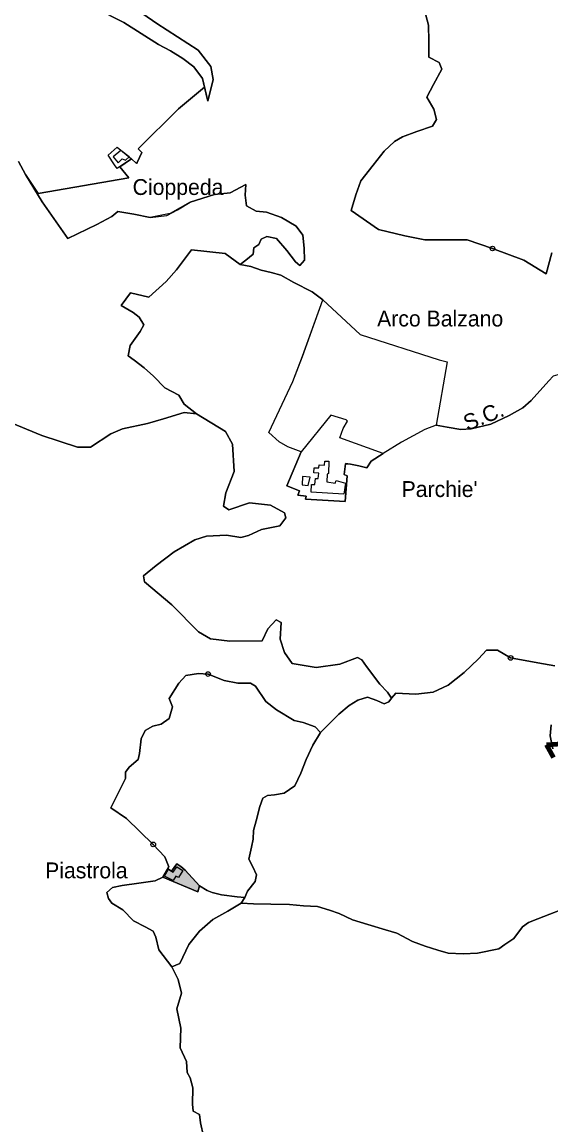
# Model space of a CAD drawing. Extents: x 645880 to 658994, y 884400 to 894744.
# Drawn here: x 652718 to 653285, y 890509 to 891691 of the extents above; entities that cross this region are included whole.
import ezdxf
from ezdxf.enums import TextEntityAlignment as Align

# ---------------------------------------------------------------- set-up
doc = ezdxf.new("R2010")
doc.units = 0
doc.header["$LTSCALE"] = 10
doc.header["$PDMODE"] = 32
doc.header["$PDSIZE"] = 5
doc.linetypes.add('MEDIUM_DASHED', pattern=[4.5, 3, -1.5])
for name, color, linetype, lineweight in [('15', 7, 'MEDIUM_DASHED', 100), ('16', 7, 'Continuous', 25), ('18', 7, 'Continuous', 25), ('2', 7, 'Continuous', 25), ('25', 7, 'Continuous', 25), ('30', 7, 'Continuous', 25), ('4', 7, 'Continuous', 25)]:
    doc.layers.add(name, color=color, linetype=linetype, lineweight=lineweight)
doc.layers.add('60', color=7, linetype='Continuous')

msp = doc.modelspace()

# ---------------------------------------------------------------- hatches: boundary and pattern name
at = {"layer": '4'}
msp.add_hatch(color=256, dxfattribs=at).paths.add_polyline_path([(652884.06, 890788.49), (652878.32, 890780.74), (652874.14, 890783.33), (652868.93, 890774.26), (652906.3, 890758.49), (652908.3, 890764.99), (652892.81, 890781.74), (652888.31, 890785.49)])

# ---------------------------------------------------------------- linework, layer by layer
at = {"layer": '15'}
msp.add_lwpolyline([(653342.43, 890919.05), (653280.25, 890916.29), (653287.62, 890902.46)], dxfattribs=at)
at = {"layer": '16'}
for points in [[(653002.43, 891823.29), (652995.41, 891834.83), (652978.65, 891842.69), (652936.47, 891856.33), (652905.12, 891785), (652894.84, 891761.93), (652888.36, 891759.3), (652861.87, 891770.32), (652845.11, 891777.66), (652834.29, 891780.28), (652817.53, 891780.28), (652808.88, 891777.66), (652802.39, 891768.22), (652800.77, 891748.29), (652802.39, 891734.65), (652826.72, 891714.2), (652862.41, 891689.55), (652906.74, 891661.23), (652920.26, 891643.4), (652922.96, 891629.76), (652917.26, 891606.21), (652913.63, 891621.31)], [(653222.34, 891448.39), (653195.31, 891457.83), (653175.85, 891457.83), (653149.9, 891457.83), (653128.27, 891462.03), (653100.12, 891468.66), (653070.87, 891489.06), (653075.72, 891505.88), (653081.13, 891521.09), (653094.39, 891537.89), (653106.26, 891552.74), (653117.39, 891563.14), (653126, 891567.97), (653141.14, 891573.74), (653157.9, 891579.51), (653162.23, 891586.85), (653159.52, 891597.87), (653151.98, 891610.78), (653158.98, 891624.09), (653168.17, 891640.67), (653165.07, 891647.75), (653154.12, 891653.46), (653154.02, 891669.83), (653153.98, 891671.79), (653153.61, 891687.95), (653150.87, 891698.56)], [(652913.56, 891621.3), (652885.76, 891598.01), (652842.38, 891555.26)], [(652842.38, 891555.26), (652846.26, 891551.26), (652841.51, 891540.57), (652840.88, 891539.64), (652835.49, 891544.67), (652822.85, 891535.96)], [(652822.85, 891535.96), (652832.63, 891524.14), (652735.13, 891507.26), (652721.82, 891527.66), (652739.66, 891498.29), (652767.23, 891458.96), (652798.05, 891474.17), (652814.27, 891482.56), (652820.75, 891488.05), (652837.95, 891485.21), (652855.25, 891481.54)], [(652855.25, 891481.54), (652873.09, 891483.82), (652884.65, 891489.7), (652898.24, 891497.93), (652924.25, 891506.33), (652941.01, 891507.91), (652957.97, 891516.94), (652957.23, 891505.59), (652958.47, 891494.24), (652969.07, 891488.32)], [(652969.07, 891488.32), (652979.92, 891487.33), (652996.19, 891481.65), (653011.86, 891472.21), (653018.89, 891462.77), (653020.51, 891448.61), (653020.85, 891435.76), (653015.92, 891430.09), (653011.32, 891433.92), (653001.86, 891446.37), (652990.77, 891458.95), (652980.51, 891461.2), (652974.25, 891458.46), (652971.86, 891452.8), (652966.45, 891449.13), (652965.86, 891442.18), (652957.97, 891435.76), (652951.81, 891431.32)], [(653040.32, 891393.42), (653029.16, 891401.86), (653009.44, 891411.84), (652995.47, 891419.82), (652985.06, 891422.71), (652974.2, 891425.14), (652963.12, 891428.91), (652951.81, 891431.32), (652935.63, 891442.84), (652899.78, 891446.87), (652883.73, 891425.53), (652872.66, 891412.83), (652854, 891396.16), (652834.44, 891400.74), (652824.26, 891387.25), (652837.24, 891379.91), (652843.72, 891374.66), (652848.74, 891366.44), (652844.81, 891359.45), (652833.99, 891344.24), (652831.83, 891333.23), (652838.28, 891328.67), (652848.98, 891320.55), (652858.83, 891311.36), (652871.18, 891298.84), (652886.22, 891290.95), (652891.81, 891281.47), (652904.91, 891270.92), (652936.23, 891252.06), (652943.79, 891238.44), (652945.37, 891209.15), (652936.6, 891186.21), (652933.81, 891172.04), (652939.59, 891168.25), (652961.73, 891175.63), (652984.46, 891173.04), (652999.22, 891165.05), (653000.81, 891159.47), (652994.23, 891151.08), (652974.69, 891146.89)], [(653286.13, 891443.68), (653279.91, 891421.22), (653255.86, 891435.8), (653222.34, 891448.39)], [(652951.81, 891431.32), (652963.12, 891428.91), (652974.2, 891425.14), (652985.06, 891422.71)], [(652985.06, 891422.71), (652995.47, 891419.82), (653009.44, 891411.84), (653029.16, 891401.86), (653040.32, 891393.42)], [(653008.17, 891305.67), (653018.55, 891332.51), (653040.32, 891393.42)], [(653040.32, 891393.42), (653080.31, 891356.08), (653165.12, 891329.09), (653173.6, 891326.82), (653161.92, 891258.86)], [(653533.65, 891387.68), (653521.69, 891378.36), (653497.31, 891373.04), (653465.84, 891363.73), (653445.45, 891357.08), (653395.81, 891338.9), (653376.75, 891334.46), (653364.34, 891332.24), (653332.87, 891331.8), (653323.56, 891330.47), (653315.58, 891325.59), (653302.29, 891317.61), (653292.53, 891312.73), (653287.22, 891311.4), (653282.78, 891306.52)], [(653282.78, 891306.52), (653287.22, 891311.4)], [(653017.39, 891230.27), (653002.93, 891235.58), (652993.58, 891241.19), (652982.51, 891251.01), (653008.17, 891305.67)], [(653161.92, 891258.86), (653173.65, 891256.85), (653188.27, 891254.18), (653199.36, 891254.85), (653220.41, 891260.17), (653240.35, 891269.26), (653254.86, 891277.69), (653263.72, 891285.23), (653282.78, 891306.52)], [(653282.78, 891306.52), (653263.72, 891285.23), (653254.86, 891277.69), (653240.35, 891269.26), (653220.41, 891260.17), (653199.36, 891254.85), (653188.27, 891254.18), (653173.65, 891256.85), (653161.92, 891258.86)], [(653161.92, 891258.86), (653149.78, 891254.42), (653124.75, 891240.63), (653104.99, 891228.57), (653092.19, 891220.27), (653087.59, 891213.07), (653078.89, 891215.37), (653070.19, 891217.17), (653064.79, 891217.67), (653063.36, 891206.09), (653066.56, 891204.72), (653064.31, 891177.02), (653021.75, 891179.7), (653022.55, 891182.64), (653013.72, 891183.98), (653015.32, 891188.54), (653001.94, 891193.89), (653017.39, 891230.27)], [(652974.69, 891146.89), (652960.73, 891140.51), (652952.55, 891138.51), (652937.31, 891141.01), (652915.71, 891139.96), (652903.3, 891135.92), (652881.15, 891123.19), (652861.71, 891108.53), (652848.27, 891097.41), (652849.46, 891091.03), (652878.58, 891066.28), (652907.07, 891037.28), (652920.03, 891029.95), (652940.8, 891027.37), (652975.3, 891027.57), (652981.59, 891040.43), (652990.45, 891050.32), (652995.84, 891047.33), (652994.64, 891029.57), (652999.43, 891015), (653007.41, 891003.42), (653033.34, 890999.03), (653058.86, 891002.62), (653077.61, 891009.61)], [(653077.61, 891009.61), (653082.19, 891007.21), (653087.38, 891000.23), (653101.54, 890981.27), (653109.91, 890972.49), (653114, 890966.12), (653118.61, 890971.6), (653140.21, 890970.55), (653158.57, 890972.65), (653174.77, 890979.98), (653192.05, 890993.6), (653207.17, 891008.27), (653215.81, 891017.7), (653227.69, 891017.7), (653241.73, 891009.32)], [(653241.73, 891009.32), (653270.89, 891004.08), (653289.25, 891000.94)], [(652917.4, 890992.08), (652907.14, 890992.61), (652893.64, 890990.51), (652886.16, 890982.14), (652875.9, 890965.9), (652879.14, 890957), (652875.9, 890944.43), (652867.26, 890938.14), (652858.08, 890936.05), (652849.98, 890931.33), (652845.66, 890922.43), (652844.04, 890906.71), (652842.42, 890900.42), (652832.7, 890892.04), (652828.92, 890886.8), (652828.92, 890879.99), (652824.06, 890870.04), (652813.26, 890848.56), (652830, 890837.04), (652858.62, 890809.28)], [(652976.26, 890859.03), (652981.11, 890861.93), (652988.68, 890862.69), (652998.94, 890864.27), (653010.28, 890872.12), (653016.76, 890885.74), (653022.7, 890900.41), (653029.72, 890915.6), (653037.82, 890929.22), (653032.42, 890935.51), (653019.46, 890940.22), (653009.74, 890942.32), (652990.84, 890953.84), (652979.5, 890962.75), (652968.16, 890978.99), (652962.76, 890982.13), (652949.26, 890982.13), (652934.68, 890985.27), (652917.4, 890992.08)], [(653285.27, 890937.41), (653284.24, 890925.92), (653287.2, 890911.94)], [(652908.3, 890764.99), (652916.32, 890760.03), (652921.68, 890757.77), (652931.97, 890755.38), (652948.6, 890753.26), (652956.86, 890752.51), (652959.8, 890759.35), (652967.9, 890769.56), (652969.52, 890776.89), (652965.55, 890785.29), (652961.16, 890793.67), (652963.85, 890806.49), (652965.74, 890814.87), (652966.28, 890824.3), (652968.98, 890834.52), (652973.02, 890850.12), (652976.26, 890859.03)], [(652858.62, 890809.28), (652871.04, 890796.18), (652875.45, 890785.47)], [(652875.45, 890785.47), (652874.14, 890783.33), (652878.32, 890780.74), (652884.06, 890788.49), (652888.31, 890785.49), (652892.81, 890781.74), (652908.3, 890764.99)], [(652868.92, 890774.26), (652860.86, 890770.27), (652843.14, 890767.8), (652825.19, 890765.34), (652815.1, 890763.09), (652808.94, 890757.94)], [(652908.3, 890764.99), (652906.3, 890758.49), (652868.93, 890774.26)], [(652956.86, 890752.51), (652948.6, 890753.26), (652931.97, 890755.38), (652921.68, 890757.77), (652916.32, 890760.03), (652908.3, 890764.99)], [(652808.94, 890757.94), (652810.84, 890751.42), (652814.34, 890746.41), (652826.22, 890739.08), (652837.56, 890727.56), (652849.95, 890720.93), (652858.59, 890716.21), (652861.29, 890709.93), (652864.67, 890696.43), (652878.57, 890677.95)], [(652878.57, 890677.95), (652887.28, 890681.48), (652896.66, 890702.01), (652908.33, 890716.26), (652922.49, 890728.83), (652938.51, 890737.69), (652952.75, 890746.48), (652956.86, 890752.51)]]:
    msp.add_lwpolyline(points, dxfattribs=at)
for p in [(653222.34, 891448.39), (653241.73, 891009.32), (652917.4, 890992.08), (652858.62, 890809.28)]:
    msp.add_point(p, dxfattribs=at)
at = {"layer": '18'}
for points in [[(652877.28, 891660.2), (652890.36, 891652.23), (652902.23, 891643.32), (652911.34, 891630.83), (652917.26, 891606.21), (652922.96, 891629.76), (652920.26, 891643.4), (652906.74, 891661.23), (652862.41, 891689.55), (652826.72, 891714.2)], [(652796.14, 891706.43), (652827.3, 891690.83), (652864.31, 891667.01), (652877.28, 891660.2)], [(653150.87, 891698.56), (653153.61, 891687.95)], [(653153.61, 891687.95), (653154.02, 891669.83), (653154.12, 891653.46), (653165.07, 891647.75), (653168.17, 891640.67), (653158.98, 891624.09), (653151.98, 891610.78), (653159.52, 891597.87), (653162.23, 891586.85), (653157.9, 891579.51), (653141.14, 891573.74), (653126, 891567.97), (653117.39, 891563.14), (653106.26, 891552.74), (653094.39, 891537.89), (653081.13, 891521.09), (653075.72, 891505.88), (653070.87, 891489.06), (653100.12, 891468.66), (653128.27, 891462.03), (653149.9, 891457.83), (653175.85, 891457.83), (653195.31, 891457.83), (653222.34, 891448.39), (653255.86, 891435.8), (653279.91, 891421.22), (653286.13, 891443.68)], [(652957.23, 891505.59), (652957.97, 891516.94), (652941.01, 891507.91), (652924.25, 891506.33), (652898.24, 891497.93), (652876.88, 891485.74), (652855.25, 891481.54), (652837.95, 891485.21), (652820.75, 891488.05), (652814.27, 891482.56), (652798.05, 891474.17), (652767.23, 891458.96), (652739.66, 891498.29), (652721.82, 891527.66), (652714.25, 891541.82)], [(652904.91, 891270.92), (652891.81, 891281.47), (652886.22, 891290.95), (652871.18, 891298.84), (652858.83, 891311.36), (652848.98, 891320.55), (652838.28, 891328.67), (652831.83, 891333.23), (652833.99, 891344.24), (652844.81, 891359.45), (652848.74, 891366.44), (652843.72, 891374.66), (652837.24, 891379.91), (652824.26, 891387.25), (652834.44, 891400.74), (652854, 891396.16), (652872.66, 891412.83), (652883.73, 891425.53), (652899.78, 891446.87), (652935.63, 891442.84), (652951.81, 891431.32), (652957.97, 891435.76), (652965.86, 891442.18), (652966.45, 891449.13), (652971.86, 891452.8), (652974.25, 891458.46), (652980.51, 891461.2), (652990.77, 891458.95), (653001.86, 891446.37), (653011.32, 891433.92), (653015.92, 891430.09), (653020.85, 891435.76), (653020.51, 891448.61), (653018.89, 891462.77), (653011.86, 891472.21), (652996.19, 891481.65), (652979.92, 891487.33), (652969.07, 891488.32), (652958.47, 891494.24), (652957.23, 891505.59)], [(652904.91, 891270.92), (652891.82, 891272.45), (652869.73, 891265.73), (652852.39, 891260.7), (652825.54, 891255.1), (652813.24, 891249.5), (652791.43, 891235.23), (652777.44, 891235.51), (652739.07, 891248.01), (652702.22, 891263.21)], [(652702.22, 891263.21), (652739.07, 891248.01), (652777.44, 891235.51), (652791.43, 891235.23), (652813.24, 891249.5), (652825.54, 891255.1), (652852.39, 891260.7), (652869.73, 891265.73), (652891.82, 891272.45), (652904.91, 891270.92)], [(653087.38, 891000.23), (653082.19, 891007.21), (653077.61, 891009.61), (653058.86, 891002.62), (653033.34, 890999.03), (653007.41, 891003.42), (652999.43, 891015), (652994.64, 891029.57), (652995.84, 891047.33), (652990.45, 891050.32), (652981.59, 891040.43), (652975.3, 891027.57), (652940.8, 891027.37), (652920.03, 891029.95), (652907.07, 891037.28), (652878.58, 891066.28), (652849.46, 891091.03), (652848.27, 891097.41), (652861.71, 891108.53), (652881.15, 891123.19), (652903.3, 891135.92), (652915.71, 891139.96), (652937.31, 891141.01), (652952.55, 891138.51), (652960.73, 891140.51), (652974.69, 891146.89), (652994.23, 891151.08), (653000.81, 891159.47), (652999.22, 891165.05), (652984.46, 891173.04), (652961.73, 891175.63), (652939.59, 891168.25), (652933.81, 891172.04), (652936.6, 891186.21), (652945.37, 891209.15), (652943.79, 891238.44), (652936.23, 891252.06), (652904.91, 891270.92)], [(653289.25, 891000.94), (653270.89, 891004.08), (653241.73, 891009.32), (653227.69, 891017.7), (653215.81, 891017.7), (653207.17, 891008.27), (653192.05, 890993.6), (653174.77, 890979.98)], [(653037.82, 890929.22), (653048.19, 890939.58), (653057.52, 890948.92), (653068.82, 890958.26), (653078.15, 890964.16), (653088.46, 890967.11), (653098.29, 890963.67), (653106.14, 890960.23), (653111.06, 890962.19), (653114, 890966.12), (653109.91, 890972.49), (653101.54, 890981.27), (653087.38, 891000.23)], [(652814.34, 890746.41), (652810.84, 890751.42), (652808.94, 890757.94), (652815.1, 890763.09), (652825.19, 890765.34), (652843.14, 890767.8), (652860.86, 890770.27), (652868.92, 890774.26), (652875.45, 890785.47), (652871.04, 890796.18), (652858.62, 890809.28), (652830, 890837.04), (652813.26, 890848.56), (652824.06, 890870.04), (652828.92, 890879.99), (652828.92, 890886.8), (652832.7, 890892.04), (652842.42, 890900.42), (652844.04, 890906.71), (652845.66, 890922.43), (652849.98, 890931.33), (652858.08, 890936.05), (652867.26, 890938.14), (652875.9, 890944.43), (652879.14, 890957), (652875.9, 890965.9), (652886.16, 890982.14), (652893.64, 890990.51), (652907.14, 890992.61), (652917.4, 890992.08)], [(652917.4, 890992.08), (652934.68, 890985.27), (652949.26, 890982.13), (652962.76, 890982.13), (652968.16, 890978.99), (652979.5, 890962.75), (652990.84, 890953.84), (653009.74, 890942.32), (653019.46, 890940.22), (653032.42, 890935.51), (653037.82, 890929.22)], [(653174.77, 890979.98), (653158.57, 890972.65), (653140.21, 890970.55), (653118.61, 890971.6), (653114, 890966.12)], [(653078.15, 890964.16), (653068.82, 890958.26), (653057.52, 890948.92)], [(653114, 890966.12), (653111.06, 890962.19), (653106.14, 890960.23), (653098.29, 890963.67), (653088.46, 890967.11), (653078.15, 890964.16)], [(653057.52, 890948.92), (653048.19, 890939.58), (653037.82, 890929.22), (653029.72, 890915.6), (653022.7, 890900.41), (653016.76, 890885.74), (653010.28, 890872.12), (652998.94, 890864.27), (652988.68, 890862.69)], [(653287.2, 890911.94), (653284.24, 890925.92), (653285.27, 890937.41)], [(652988.68, 890862.69), (652981.11, 890861.93), (652976.26, 890859.03), (652973.02, 890850.12), (652968.98, 890834.52), (652966.28, 890824.3), (652965.74, 890814.87), (652963.85, 890806.49), (652961.16, 890793.67), (652965.55, 890785.29), (652969.52, 890776.89), (652967.9, 890769.56), (652959.8, 890759.35), (652956.86, 890752.51), (652952.75, 890746.48)], [(652858.59, 890716.21), (652849.95, 890720.93), (652837.56, 890727.56), (652826.22, 890739.08), (652814.34, 890746.41)], [(653136.72, 890705.23), (653119.84, 890714.2), (653107.66, 890717.84), (653088.65, 890723.39), (653072.19, 890728.53), (653058.09, 890735.36), (653047.62, 890738.78), (653034.59, 890742.63), (653019.84, 890743.48), (653004.67, 890744.77), (652984.8, 890745.19), (652966, 890745.63), (652952.75, 890746.48), (652938.51, 890737.69), (652922.49, 890728.83), (652908.33, 890716.26), (652896.66, 890702.01), (652887.28, 890681.48), (652878.57, 890677.95)], [(652952.75, 890746.48), (652966, 890745.63), (652984.8, 890745.19), (653004.67, 890744.77), (653019.84, 890743.48), (653034.59, 890742.63), (653047.62, 890738.78), (653058.09, 890735.36), (653072.19, 890728.53), (653088.65, 890723.39), (653107.66, 890717.84), (653119.84, 890714.2), (653136.72, 890705.23)], [(653294.84, 890739), (653283.94, 890734.72), (653271.12, 890729.59), (653260.87, 890725.53), (653254.67, 890721.04), (653245.06, 890708.29), (653235.45, 890701.88), (653229.24, 890697.31), (653206.38, 890692.82), (653191, 890691.97), (653174.97, 890692.83), (653163.86, 890696.03), (653150.19, 890700.1), (653136.72, 890705.23)], [(653136.72, 890705.23), (653150.19, 890700.1), (653163.86, 890696.03), (653174.97, 890692.83), (653191, 890691.97), (653206.38, 890692.82), (653229.24, 890697.31), (653235.45, 890701.88), (653245.06, 890708.29), (653254.67, 890721.04), (653260.87, 890725.53), (653271.12, 890729.59), (653283.94, 890734.72), (653294.84, 890739)], [(652912.43, 890496.64), (652909.32, 890510.62), (652908.42, 890519.61), (652901.62, 890523.2), (652900.59, 890530.9), (652901.24, 890548.23), (652898.16, 890558.89), (652894.93, 890564.8), (652894.18, 890576.48), (652887.38, 890591.12), (652888.15, 890612.17), (652884.05, 890633.1), (652888.84, 890649.71), (652885.41, 890664.48), (652878.57, 890677.95), (652864.67, 890696.43), (652861.29, 890709.93), (652858.59, 890716.21)], [(652878.57, 890677.95), (652885.41, 890664.48), (652888.84, 890649.71), (652884.05, 890633.1), (652888.15, 890612.17), (652887.38, 890591.12), (652894.18, 890576.48), (652894.93, 890564.8), (652898.16, 890558.89), (652901.24, 890548.23), (652900.59, 890530.9), (652901.62, 890523.2), (652908.42, 890519.61), (652909.32, 890510.62), (652912.43, 890496.64)]]:
    msp.add_lwpolyline(points, dxfattribs=at)
msp.add_point((652917.4, 890992.08), dxfattribs=at)
at = {"layer": '2'}
for points in [[(652823.75, 891553.57), (652815.61, 891546.59), (652821.14, 891540.34), (652825.2, 891544.56), (652828.84, 891543.25), (652832.91, 891546.74)], [(653042.49, 891220.33), (653047.05, 891220.5), (653046.54, 891206.98), (653045.24, 891206.55), (653044.73, 891198.19), (653053.86, 891196.64), (653054.8, 891199.48), (653064.88, 891196.64), (653062.9, 891184.83), (653027.85, 891187.07), (653028.28, 891195.26), (653031.9, 891195.43), (653032.58, 891201.63), (653035.43, 891201.63), (653036.03, 891207.41), (653030.69, 891207.67), (653031.12, 891213.27), (653036.03, 891213.01), (653036.46, 891216.28), (653042.14, 891216.02)], [(653018.73, 891203.88), (653018.13, 891194.83), (653024.67, 891194.14), (653026.91, 891203.19)]]:
    msp.add_lwpolyline(points, close=True, dxfattribs=at)
for points in [[(653058.79, 891245.45), (653062.33, 891255.36), (653067.07, 891263.08), (653065.32, 891264.5), (653048.89, 891269.77), (653017.34, 891230.29)], [(653017.34, 891230.29), (653001.94, 891193.89), (653015.32, 891188.54), (653013.72, 891183.98), (653022.55, 891182.64), (653021.75, 891179.7), (653064.31, 891177.02), (653066.56, 891204.72), (653063.36, 891206.09), (653064.74, 891217.61), (653070.19, 891217.11), (653078.89, 891215.37), (653087.6, 891213.04), (653092.17, 891220.28), (653104.98, 891228.51), (653058.79, 891245.45)]]:
    msp.add_lwpolyline(points, dxfattribs=at)
at = {"layer": '25'}
for points in [[(652911.34, 891630.83), (652902.23, 891643.32), (652890.36, 891652.23), (652877.28, 891660.2), (652864.31, 891667.01), (652827.3, 891690.83), (652796.14, 891706.43)], [(652842.38, 891555.26), (652885.76, 891598.01), (652913.56, 891621.3), (652911.34, 891630.83)], [(652714.25, 891541.82), (652721.82, 891527.66), (652735.13, 891507.26), (652832.63, 891524.14), (652822.85, 891535.96), (652835.49, 891544.67), (652840.88, 891539.64), (652841.51, 891540.57), (652846.26, 891551.26), (652842.38, 891555.26)]]:
    msp.add_lwpolyline(points, dxfattribs=at)
at = {"layer": '30'}
msp.add_lwpolyline([(653008.17, 891305.67), (653018.79, 891332.94), (653040.32, 891393.42), (653080.31, 891356.08), (653165.12, 891329.09), (653173.6, 891326.82), (653161.92, 891258.86), (653149.78, 891254.42), (653124.75, 891240.63), (653104.99, 891228.57), (653058.79, 891245.47), (653062.33, 891255.36), (653067.07, 891263.08), (653065.32, 891264.5), (653048.89, 891269.77), (653017.39, 891230.27), (653002.93, 891235.58), (652993.58, 891241.19), (652982.51, 891251.01)], close=True, dxfattribs=at)
at = {"layer": '4'}
for points in [[(652810.23, 891548.63), (652819.97, 891557.06), (652835.49, 891544.67), (652820.09, 891534.07), (652817.26, 891538.19)], [(652884.06, 890788.49), (652878.32, 890780.74), (652874.14, 890783.33), (652868.93, 890774.26), (652906.3, 890758.49), (652908.3, 890764.99), (652892.81, 890781.74), (652888.31, 890785.49)], [(652875.12, 890782.64), (652879.91, 890779.63), (652883.81, 890785.44), (652890.31, 890781.54), (652885.59, 890773.94), (652882.85, 890775.45), (652880.12, 890770.66), (652870.75, 890775.31)]]:
    msp.add_lwpolyline(points, close=True, dxfattribs=at)

# ---------------------------------------------------------------- texts
at = {"layer": '60'}
for s, p in [('Cioppeda', (652885.21, 891505.79)), ('Arco Balzano', (653166.25, 891364.75)), ("Parchie'", (653165.6, 891181.88)), ('Piastrola', (652786.97, 890772.97))]:
    msp.add_text(s, height=17, dxfattribs=at).set_placement(p, align=Align.CENTER)
msp.add_text("S.C.            DEL              PARCHIE'", height=17, rotation=22.275, dxfattribs=at).set_placement((653361.15, 891320.37), align=Align.CENTER)

doc.saveas('drawing.dxf')
